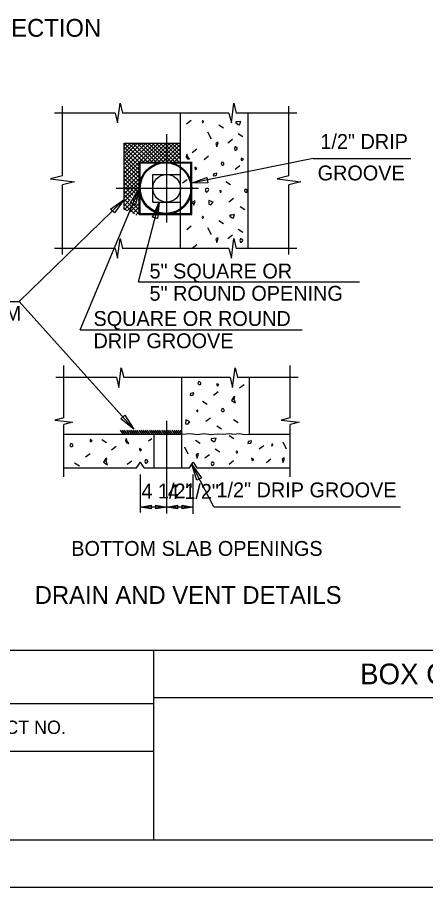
# Model space of a CAD drawing. Extents: x 0 to 34, y 0 to 23.5.
# Drawn here: x 20.81 to 25.11, y 0 to 9.16 of the extents above; entities that cross this region are included whole.
import ezdxf

# ---------------------------------------------------------------- set-up
doc = ezdxf.new("R2010")
doc.units = 0
for name, color, linetype in [('BORDER_ANNO_Cutsheet', 7, 'Continuous'), ('BRDG_ANNO_Anno-Sheet', 7, 'Continuous'), ('BRDG_ANNO_General-Notes', 7, 'Continuous'), ('BRDG_BASE_Dtlctrln', 7, 'Continuous'), ('BRDG_BASE_Hidden-Line', 7, 'Continuous'), ('BRDG_BASE_Obj-Line', 7, 'Continuous'), ('BRDG_BASE_Pattern', 7, 'Continuous')]:
    doc.layers.add(name, color=color, linetype=linetype)

msp = doc.modelspace()

# ---------------------------------------------------------------- linework, layer by layer
at = {"layer": 'BORDER_ANNO_Cutsheet'}
msp.add_lwpolyline([(0, 22), (34, 22), (34, 0), (0, 0)], close=True, dxfattribs=at)
at = {"layer": 'BRDG_ANNO_Anno-Sheet'}
for p, q in [((19.25, 2.5), (33.5, 2.5)), ((22.25, 0.5), (22.25, 2.5)), ((19.25, 1.9375), (22.25, 1.9375)), ((22.25, 2), (30.25, 2)), ((19.25, 1.4375), (22.25, 1.4375))]:
    msp.add_line(p, q, dxfattribs=at)
msp.add_lwpolyline([(1.5, 21.5), (33.5, 21.5), (33.5, 0.5), (1.5, 0.5)], close=True, dxfattribs=at)
at = {"layer": 'BRDG_ANNO_General-Notes'}
for p, q in [((23.9302, 7.6753), (22.6452, 7.4156)), ((23.9302, 7.6753), (24.9576, 7.6753)), ((22.6452, 7.4156), (22.8071, 7.4774)), ((22.8184, 7.4215), (22.6452, 7.4156)), ((22.8071, 7.4774), (22.8184, 7.4215)), ((21.4729, 5.8739), (22.0956, 7.3578)), ((22.0032, 7.2111), (22.0956, 7.3578)), ((22.0956, 7.3578), (22.0557, 7.1891)), ((20.8304, 6.1721), (21.9379, 7.2429)), ((21.7952, 7.1445), (21.9379, 7.2429)), ((21.9379, 7.2429), (21.8347, 7.1036)), ((22.0557, 7.1891), (22.0032, 7.2111)), ((22.0894, 6.3784), (22.3048, 7.2174)), ((22.2347, 7.0589), (22.3048, 7.2174)), ((22.3048, 7.2174), (22.2899, 7.0447)), ((21.8347, 7.1036), (21.7952, 7.1445)), ((22.2899, 7.0447), (22.2347, 7.0589)), ((22.0894, 6.3784), (24.4154, 6.3784)), ((19.5549, 6.1721), (20.8304, 6.1721)), ((20.8304, 6.1721), (22.0379, 4.826)), ((21.4729, 5.8739), (23.8114, 5.8739)), ((21.9024, 4.9343), (21.9449, 4.9723)), ((21.9449, 4.9723), (22.0379, 4.826)), ((22.0379, 4.826), (21.9024, 4.9343)), ((22.8813, 4.0103), (22.6494, 4.4538)), ((22.7034, 4.2891), (22.6494, 4.4538)), ((22.6494, 4.4538), (22.7539, 4.3155)), ((22.1087, 3.9479), (22.1087, 4.3503)), ((22.6629, 3.9363), (22.6629, 4.3503)), ((22.7539, 4.3155), (22.7034, 4.2891)), ((22.1069, 4.0066), (22.2209, 4.0256)), ((22.2209, 3.9876), (22.1069, 4.0066)), ((22.1087, 4.0075), (22.6629, 4.0075)), ((22.2209, 4.0256), (22.2209, 3.9876)), ((22.2719, 3.9876), (22.2719, 4.0256)), ((22.2719, 4.0256), (22.3859, 4.0066)), ((22.3859, 4.0066), (22.2719, 3.9876)), ((22.3859, 4.0066), (22.4999, 4.0256)), ((22.4999, 3.9876), (22.3859, 4.0066)), ((22.4999, 4.0256), (22.4999, 3.9876)), ((22.5473, 3.9876), (22.5473, 4.0256)), ((22.5473, 4.0256), (22.6613, 4.0066)), ((22.6613, 4.0066), (22.5473, 3.9876)), ((22.8813, 4.0103), (24.8498, 4.0103))]:
    msp.add_line(p, q, dxfattribs=at)
at = {"layer": 'BRDG_BASE_Dtlctrln'}
for p, q in [((21.8548, 7.3632), (22.7191, 7.3632)), ((22.3858, 3.9403), (22.3858, 4.9129))]:
    msp.add_line(p, q, dxfattribs=at)
at = {"layer": 'BRDG_BASE_Hidden-Line'}
for p, q in [((22.0962, 7.6394), (22.6505, 7.6394)), ((22.0962, 7.0861), (22.0962, 7.6394)), ((22.1061, 7.0969), (22.1061, 7.6305)), ((22.1061, 7.6305), (22.6405, 7.6305)), ((22.6405, 7.0969), (22.6405, 7.6305)), ((22.6504, 7.0861), (22.6504, 7.6403)), ((22.0962, 7.0856), (22.6504, 7.0856)), ((22.1061, 7.0969), (22.6405, 7.0969))]:
    msp.add_line(p, q, dxfattribs=at)
for centre, radius in [((22.3733, 7.3622), 0.2771), ((22.3733, 7.3643), 0.2672)]:
    msp.add_circle(centre, radius, dxfattribs=at)
at = {"layer": 'BRDG_BASE_Obj-Line'}
for p, q in [((21.8691, 8.0507), (21.8952, 8.2591)), ((21.8952, 8.2591), (21.9212, 8.1549)), ((23.067, 8.0507), (23.0931, 8.2591)), ((23.0931, 8.2591), (23.1191, 8.1549)), ((21.8431, 8.1549), (21.2051, 8.1549)), ((21.2884, 7.4934), (21.2884, 8.2278)), ((21.8431, 8.1549), (21.8691, 8.0507)), ((23.041, 8.1549), (21.9212, 8.1549)), ((22.5316, 6.7299), (22.5316, 8.1549)), ((23.041, 8.1549), (23.067, 8.0507)), ((23.7571, 8.1549), (23.1191, 8.1549)), ((23.2441, 6.7299), (23.2441, 8.1549)), ((23.6738, 7.4934), (23.6738, 8.2278)), ((22.3858, 7.0032), (22.3858, 7.932)), ((21.9379, 7.8382), (22.5316, 7.8382)), ((21.9379, 7.1402), (21.9379, 7.8382)), ((22.5129, 7.8382), (22.5316, 7.8382)), ((21.2884, 7.4934), (21.1634, 7.4622)), ((21.1634, 7.4622), (21.4134, 7.4309)), ((21.4134, 7.4309), (21.2884, 7.3997)), ((22.2399, 7.5091), (22.5316, 7.5091)), ((22.2399, 7.2174), (22.2399, 7.5091)), ((23.6738, 7.4934), (23.5488, 7.4622)), ((23.5488, 7.4622), (23.7988, 7.4309)), ((23.7988, 7.4309), (23.6738, 7.3997)), ((21.2884, 6.6653), (21.2884, 7.3997)), ((23.6738, 6.6653), (23.6738, 7.3997)), ((22.2399, 7.2174), (22.5316, 7.2174)), ((21.8691, 6.6257), (21.8952, 6.8341)), ((21.8952, 6.8341), (21.9212, 6.7299)), ((23.067, 6.6257), (23.0931, 6.8341)), ((23.0931, 6.8341), (23.1191, 6.7299)), ((21.8431, 6.7299), (21.2051, 6.7299)), ((21.8431, 6.7299), (21.8691, 6.6257)), ((23.041, 6.7299), (21.9212, 6.7299)), ((23.041, 6.7299), (23.067, 6.6257)), ((23.7571, 6.7299), (23.1191, 6.7299)), ((21.3009, 4.9459), (21.3009, 5.4967)), ((21.8816, 5.2649), (21.9077, 5.4732)), ((21.9077, 5.4732), (21.9337, 5.3691)), ((23.0795, 5.2649), (23.1056, 5.4732)), ((23.1056, 5.4732), (23.1316, 5.3691)), ((23.6863, 4.9459), (23.6863, 5.4967)), ((21.8556, 5.3691), (21.2176, 5.3691)), ((21.8556, 5.3691), (21.8816, 5.2649)), ((23.0535, 5.3691), (21.9337, 5.3691)), ((22.5441, 4.4191), (22.5441, 5.3691)), ((23.0535, 5.3691), (23.0795, 5.2649)), ((23.7696, 5.3691), (23.1316, 5.3691)), ((23.2566, 4.7753), (23.2566, 5.3691)), ((21.3009, 4.9459), (21.2071, 4.9224)), ((21.2071, 4.9224), (21.3946, 4.899)), ((21.3946, 4.899), (21.3009, 4.8756)), ((21.3009, 4.3248), (21.3009, 4.8756)), ((23.6863, 4.9459), (23.5926, 4.9224)), ((23.5926, 4.9224), (23.7801, 4.899)), ((23.7801, 4.899), (23.6863, 4.8756)), ((23.6863, 4.3248), (23.6863, 4.8756)), ((21.3009, 4.7753), (22.5441, 4.7753)), ((22.2524, 4.4191), (22.2524, 4.7753)), ((23.2566, 4.7753), (23.6863, 4.7753)), ((21.3009, 4.4191), (22.069, 4.4191)), ((22.069, 4.4191), (22.1087, 4.4774)), ((22.1478, 4.4186), (22.1087, 4.4774)), ((22.1478, 4.4191), (22.6251, 4.4191)), ((22.6251, 4.4191), (22.6629, 4.4774)), ((22.6629, 4.4774), (22.7035, 4.4179)), ((22.7035, 4.4191), (23.6863, 4.4191))]:
    msp.add_line(p, q, dxfattribs=at)
for points in [[(22.5441, 4.7753), (22.6369, 4.7807), (22.7074, 4.7706), (22.7797, 4.7799), (22.8485, 4.7706), (22.919, 4.7791), (22.9829, 4.7723), (23.0433, 4.7807), (23.092, 4.7723), (23.1507, 4.7799), (23.2079, 4.7706), (23.2566, 4.7753)], [(23.2566, 4.7753), (23.2548, 4.7755)]]:
    msp.add_lwpolyline(points, dxfattribs=at)
msp.add_circle((22.3858, 7.3632), 0.1458, dxfattribs=at)
at = {"layer": 'BRDG_BASE_Pattern'}
for p, q in [((22.6423, 8.0756), (22.5942, 8.039)), ((22.9335, 8.0292), (22.983, 7.998)), ((22.816, 7.9584), (22.8527, 7.8849)), ((23.1399, 7.9389), (23.1894, 7.9077)), ((21.9377, 7.8092), (21.967, 7.8385)), ((21.938, 7.796), (22.0963, 7.6386)), ((21.9387, 7.8391), (22.1392, 7.6397)), ((21.9389, 7.6568), (22.121, 7.838)), ((21.9401, 7.7734), (22.0052, 7.8382)), ((21.9404, 7.7373), (22.0423, 7.8387)), ((21.9416, 7.7017), (22.0787, 7.8382)), ((21.9668, 7.6409), (22.1652, 7.8382)), ((21.9842, 7.8388), (22.1821, 7.6418)), ((22.0119, 7.6409), (22.211, 7.8389)), ((22.0306, 7.8377), (22.2279, 7.6412)), ((22.0572, 7.6409), (22.256, 7.8389)), ((22.0736, 7.837), (22.2707, 7.6409)), ((22.0996, 7.6409), (22.2981, 7.8384)), ((22.113, 7.8388), (22.3115, 7.6414)), ((22.1394, 7.6395), (22.3396, 7.8385)), ((22.1554, 7.8382), (22.3532, 7.6414)), ((22.1826, 7.6409), (22.3816, 7.8387)), ((22.1954, 7.8372), (22.3927, 7.6409)), ((22.2216, 7.6409), (22.4198, 7.8381)), ((22.2336, 7.8385), (22.4323, 7.6409)), ((22.2612, 7.6409), (22.4593, 7.8379)), ((22.2753, 7.8378), (22.4748, 7.6394)), ((22.3021, 7.6409), (22.5001, 7.8377)), ((22.3179, 7.8383), (22.5179, 7.6394)), ((22.3452, 7.6409), (22.5311, 7.8258)), ((22.3598, 7.8386), (22.5316, 7.6677)), ((22.4006, 7.8377), (22.5316, 7.7075)), ((22.4406, 7.8387), (22.5316, 7.7481)), ((22.4808, 7.8382), (22.5303, 7.789)), ((23.0794, 7.8758), (23.0313, 7.8392)), ((21.9379, 7.754), (22.0964, 7.5962)), ((21.9383, 7.712), (22.0962, 7.555)), ((22.3876, 7.6409), (22.5316, 7.7841)), ((22.4273, 7.6409), (22.5316, 7.7447)), ((22.4683, 7.6409), (22.5317, 7.7039)), ((22.7028, 7.7739), (22.6547, 7.7372)), ((22.8271, 7.6999), (22.779, 7.6633)), ((21.937, 7.6334), (22.0961, 7.4753)), ((21.9372, 7.5215), (22.0572, 7.6409)), ((21.9372, 7.4792), (22.0962, 7.6375)), ((21.9375, 7.5667), (22.0119, 7.6409)), ((21.9379, 7.6121), (21.9668, 7.6409)), ((21.938, 7.673), (22.0959, 7.5161)), ((22.0982, 7.6394), (22.0996, 7.6409)), ((22.5238, 7.6406), (22.5321, 7.6489)), ((21.9371, 7.4335), (22.0962, 7.5918)), ((21.9372, 7.3904), (22.0961, 7.5484)), ((21.938, 7.5903), (22.096, 7.4334)), ((21.9384, 7.5466), (22.0963, 7.3896)), ((23.156, 7.5975), (23.1079, 7.5609)), ((21.9369, 7.3456), (22.0961, 7.5039)), ((21.9369, 7.2636), (22.0961, 7.4219)), ((21.9373, 7.4236), (22.0519, 7.3098)), ((21.9377, 7.4646), (22.0707, 7.3324)), ((21.9379, 7.3036), (22.0964, 7.4612)), ((21.938, 7.5059), (22.096, 7.349)), ((22.601, 7.4532), (22.5529, 7.4166)), ((23.0078, 7.4335), (23.0573, 7.4023)), ((21.938, 7.3813), (22.0326, 7.2874)), ((21.938, 7.3369), (22.0144, 7.261)), ((21.9387, 7.2234), (22.0971, 7.381)), ((21.9377, 7.2474), (22.0965, 7.0896)), ((21.938, 7.2921), (21.9966, 7.234)), ((21.9383, 7.1796), (22.0024, 7.2434)), ((22.0285, 7.2469), (22.0635, 7.2121)), ((22.0314, 7.2288), (22.0765, 7.274)), ((22.0464, 7.2737), (22.0708, 7.2494)), ((22.0617, 7.3001), (22.0783, 7.2836)), ((22.0863, 7.2414), (22.0961, 7.2511)), ((22.0869, 7.2751), (22.0962, 7.2658)), ((22.0891, 7.2866), (22.0962, 7.2936)), ((22.0919, 7.3115), (22.0962, 7.3071)), ((23.0897, 7.2549), (23.0416, 7.2183)), ((21.9373, 7.1534), (21.9656, 7.1253)), ((21.9384, 7.2006), (22.047, 7.0926)), ((21.939, 7.1373), (22.019, 7.2168)), ((21.974, 7.1296), (22.0485, 7.2037)), ((22.0021, 7.1136), (22.0964, 7.2074)), ((22.0129, 7.2178), (22.0962, 7.135)), ((22.0304, 7.0982), (22.0954, 7.163)), ((22.0595, 7.2146), (22.0693, 7.2244)), ((22.0787, 7.197), (22.096, 7.1799)), ((22.0849, 7.2354), (22.096, 7.2244)), ((23.1586, 7.1717), (23.2082, 7.1404)), ((22.0589, 7.0809), (22.0961, 7.1179)), ((22.9335, 7.0219), (22.983, 6.9906)), ((22.6445, 6.9622), (22.5964, 6.9256)), ((22.816, 6.9511), (22.8527, 6.8776)), ((23.1399, 6.9316), (23.1894, 6.9003)), ((23.0794, 6.8684), (23.0313, 6.8318)), ((22.7028, 6.7665), (22.6547, 6.7299)), ((23.2006, 5.2935), (23.1524, 5.2569)), ((22.927, 5.2188), (22.8789, 5.1822)), ((22.764, 5.1227), (22.8135, 5.0915)), ((22.8459, 4.9441), (22.7978, 4.9074)), ((22.9148, 4.8608), (22.9644, 4.8296)), ((23.0884, 4.9291), (23.1378, 4.8981)), ((21.8956, 4.8149), (21.9235, 4.7762)), ((21.9172, 4.8149), (21.9452, 4.7763)), ((21.939, 4.8149), (21.9669, 4.7763)), ((21.9607, 4.8149), (21.9886, 4.7763)), ((21.9824, 4.815), (22.0103, 4.7763)), ((22.0041, 4.815), (22.032, 4.7763)), ((22.0258, 4.815), (22.0537, 4.7763)), ((22.0475, 4.8151), (22.0754, 4.7764)), ((22.0692, 4.8151), (22.0971, 4.7764)), ((22.0909, 4.8151), (22.1189, 4.7764)), ((22.1127, 4.8151), (22.1405, 4.7764)), ((22.1344, 4.8151), (22.1622, 4.7764)), ((22.1561, 4.8151), (22.184, 4.7764)), ((22.1778, 4.8152), (22.2057, 4.7765)), ((22.1995, 4.8152), (22.2274, 4.7765)), ((22.2212, 4.8152), (22.2491, 4.7765)), ((22.2429, 4.8152), (22.2708, 4.7765)), ((22.2646, 4.8152), (22.2926, 4.7765)), ((22.2864, 4.8152), (22.3143, 4.7765)), ((22.3081, 4.8152), (22.336, 4.7765)), ((22.3297, 4.8153), (22.3577, 4.7766)), ((22.3515, 4.8153), (22.3794, 4.7766)), ((22.3732, 4.8153), (22.4011, 4.7766)), ((22.3949, 4.8153), (22.4228, 4.7766)), ((22.4166, 4.8153), (22.4445, 4.7766)), ((22.4385, 4.8149), (22.4665, 4.7762)), ((22.4603, 4.8149), (22.4882, 4.7762)), ((22.481, 4.8149), (22.509, 4.7762)), ((22.5034, 4.8149), (22.5313, 4.7762)), ((22.5241, 4.8149), (22.5441, 4.7872)), ((21.7008, 4.7165), (21.7503, 4.6852)), ((22.2274, 4.7255), (22.1957, 4.7014)), ((22.6897, 4.711), (22.7392, 4.6798)), ((23.0434, 4.7601), (23.0929, 4.7288)), ((23.6075, 4.6941), (23.6442, 4.6205)), ((21.8528, 4.6424), (21.8046, 4.6058)), ((22.5722, 4.6403), (22.6089, 4.5667)), ((22.8961, 4.6207), (22.9456, 4.5895)), ((23.4091, 4.6514), (23.3609, 4.6147)), ((21.5792, 4.5677), (21.5311, 4.5311)), ((22.0178, 4.4912), (21.9697, 4.4546)), ((22.8356, 4.5576), (22.7875, 4.521)), ((23.0903, 4.4926), (23.0421, 4.456)), ((23.4835, 4.5095), (23.4354, 4.4729)), ((21.4162, 4.4716), (21.4657, 4.4404))]:
    msp.add_line(p, q, dxfattribs=at)
for points in [[(22.7591, 8.0634), (22.762, 8.0542), (22.7646, 8.0542), (22.7684, 8.0552), (22.7711, 8.0578), (22.7737, 8.0634), (22.773, 8.069), (22.7684, 8.0699), (22.7664, 8.0718), (22.7628, 8.0718)], [(23.1377, 8.063), (23.1156, 8.0611), (23.1156, 8.0501), (23.1395, 8.0335), (23.1525, 8.0317), (23.1654, 8.0666)], [(22.9021, 7.8336), (22.9135, 7.8004), (22.9135, 7.804), (22.9282, 7.841), (22.9244, 7.8483)], [(23.0987, 7.7819), (23.1045, 7.7635), (23.1098, 7.7635), (23.1173, 7.7653), (23.1228, 7.7707), (23.1281, 7.7819), (23.1266, 7.7929), (23.1173, 7.7948), (23.1134, 7.7986), (23.1061, 7.7986)], [(22.5936, 7.7145), (22.5896, 7.6938), (22.6033, 7.6735), (22.6264, 7.669), (22.608, 7.6933), (22.6001, 7.7186)], [(22.9674, 7.6379), (22.9582, 7.6177), (22.969, 7.6064), (22.9822, 7.6064), (22.9877, 7.6123), (22.9877, 7.6231), (22.9858, 7.6284), (22.9801, 7.6343)], [(23.1704, 7.6795), (23.1695, 7.6597), (23.1815, 7.6569), (23.193, 7.6703)], [(22.6827, 7.5859), (22.6864, 7.5601), (22.7048, 7.5712)], [(22.8805, 7.5143), (22.8768, 7.4922), (22.9026, 7.4959), (22.9099, 7.4995), (22.9136, 7.5217)], [(22.7961, 7.3583), (22.7961, 7.3304), (22.8087, 7.3214), (22.8126, 7.325), (22.8234, 7.3361), (22.8308, 7.3509), (22.8255, 7.3583), (22.8181, 7.3618), (22.8145, 7.3618), (22.8072, 7.3598)], [(22.949, 7.3385), (22.9444, 7.3284), (22.9498, 7.3228), (22.9564, 7.3228), (22.9591, 7.3257), (22.9591, 7.3311), (22.9582, 7.3337), (22.9554, 7.3367)], [(23.2135, 7.3541), (23.2042, 7.3339), (23.2151, 7.3227), (23.2283, 7.3227), (23.2337, 7.3285), (23.2337, 7.3393), (23.2319, 7.3446), (23.2261, 7.3506)], [(22.6585, 7.217), (22.6699, 7.1838), (22.6699, 7.1873), (22.6846, 7.2244), (22.6808, 7.2317)], [(22.8298, 7.2346), (22.828, 7.195), (22.8519, 7.1894), (22.8749, 7.2161)], [(22.7591, 7.0561), (22.762, 7.0469), (22.7646, 7.0469), (22.7684, 7.0478), (22.7711, 7.0505), (22.7737, 7.0561), (22.773, 7.0616), (22.7684, 7.0626), (22.7664, 7.0645), (22.7628, 7.0645)], [(23.0733, 7.0814), (23.0512, 7.0795), (23.0512, 7.0685), (23.0752, 7.052), (23.0881, 7.0501), (23.101, 7.0851)], [(22.9021, 6.8263), (22.9135, 6.7931), (22.9135, 6.7967), (22.9282, 6.8336), (22.9244, 6.841)], [(23.1567, 6.8133), (23.1625, 6.7948), (23.1678, 6.7948), (23.1753, 6.7967), (23.1807, 6.802), (23.1861, 6.8133), (23.1846, 6.8242), (23.1753, 6.8261), (23.1714, 6.8299), (23.1641, 6.8299)], [(22.7236, 5.327), (22.7144, 5.3068), (22.7252, 5.2956), (22.7384, 5.2956), (22.7439, 5.3015), (22.7439, 5.3122), (22.742, 5.3176), (22.7363, 5.3235)], [(22.9131, 5.3056), (22.9122, 5.2858), (22.9242, 5.2831), (22.9357, 5.2964)], [(22.6367, 5.2034), (22.633, 5.1814), (22.6588, 5.1851), (22.6661, 5.1887), (22.6698, 5.2108)], [(23.094, 5.1678), (23.0682, 5.1292), (23.1115, 5.1033), (23.0957, 5.1383), (23.1024, 5.1704)], [(22.9697, 5.0433), (22.9604, 5.0231), (22.9712, 5.0118), (22.9845, 5.0118), (22.9899, 5.0177), (22.9899, 5.0285), (22.9881, 5.0338), (22.9823, 5.0397)], [(22.7052, 5.0277), (22.7006, 5.0176), (22.706, 5.0119), (22.7126, 5.0119), (22.7153, 5.0148), (22.7153, 5.0203), (22.7144, 5.0229), (22.7116, 5.0259)], [(22.586, 4.9238), (22.5842, 4.8842), (22.6081, 4.8786), (22.6311, 4.9053)], [(21.3758, 4.6759), (21.3666, 4.6557), (21.3774, 4.6445), (21.3906, 4.6445), (21.396, 4.6504), (21.396, 4.6611), (21.3942, 4.6665), (21.3885, 4.6724)], [(21.5788, 4.7176), (21.5779, 4.6978), (21.5898, 4.695), (21.6014, 4.7083)], [(21.9553, 4.723), (21.9512, 4.7023), (21.9649, 4.682), (21.988, 4.6774), (21.9696, 4.7018), (21.9617, 4.7271)], [(22.8779, 4.7276), (22.8558, 4.7257), (22.8558, 4.7146), (22.8797, 4.6981), (22.8927, 4.6963), (22.9056, 4.7312)], [(23.2456, 4.6976), (23.2419, 4.6756), (23.2678, 4.6793), (23.2751, 4.6829), (23.2787, 4.705)], [(22.0994, 4.624), (22.1031, 4.5982), (22.1216, 4.6093)], [(23.1217, 4.5946), (23.1171, 4.5845), (23.1225, 4.5789), (23.1291, 4.5789), (23.1318, 4.5818), (23.1318, 4.5872), (23.1309, 4.5899), (23.1281, 4.5929)], [(23.4893, 4.6614), (23.4922, 4.6522), (23.4949, 4.6522), (23.4986, 4.6531), (23.5014, 4.6558), (23.504, 4.6614), (23.5033, 4.6669), (23.4986, 4.6679), (23.4967, 4.6698), (23.493, 4.6698)], [(21.7461, 4.5167), (21.7204, 4.4781), (21.7637, 4.4522), (21.7479, 4.4872), (21.7546, 4.5193)], [(22.1566, 4.4877), (22.1624, 4.4692), (22.1677, 4.4692), (22.1752, 4.471), (22.1806, 4.4764), (22.186, 4.4877), (22.1845, 4.4986), (22.1752, 4.5005), (22.1713, 4.5043), (22.164, 4.5043)], [(22.6955, 4.5547), (22.7069, 4.5215), (22.7069, 4.5251), (22.7216, 4.562), (22.7179, 4.5694)], [(23.2806, 4.5209), (23.2843, 4.4951), (23.3028, 4.5061)], [(23.6022, 4.509), (23.6136, 4.4758), (23.6136, 4.4794), (23.6283, 4.5164), (23.6246, 4.5237)], [(22.8549, 4.4638), (22.8607, 4.4453), (22.866, 4.4453), (22.8735, 4.4471), (22.879, 4.4525), (22.8843, 4.4638), (22.8828, 4.4747), (22.8735, 4.4766), (22.8696, 4.4804), (22.8623, 4.4804)]]:
    msp.add_lwpolyline(points, close=True, dxfattribs=at)

# ---------------------------------------------------------------- texts
at = {"layer": 'BRDG_ANNO_Anno-Sheet'}
for s, height, p in [('BOX GIRDER DETAILS', 0.218126, (24.4227, 2.1406)), ('PROJECT NO.', 0.140625, (20.0591, 1.6175))]:
    msp.add_text(s, height=height, dxfattribs=at).set_placement(p)
at = {"layer": 'BRDG_ANNO_General-Notes'}
for s, height, p in [('INTERMEDIATE DIAPHRAGM SECTION', 0.1875, (17.056, 8.9581)), ('1/2" DRIP', 0.15625, (24.0047, 7.7774)), ('GROOVE', 0.15625, (23.9755, 7.446)), ('5" SQUARE OR', 0.15625, (22.2047, 6.4132)), ('5" ROUND OPENING', 0.15625, (22.2047, 6.1788)), ('ALUMINUM', 0.15625, (19.7393, 5.9686)), ('SQUARE OR ROUND', 0.15625, (21.6147, 5.9137)), ('DRIP GROOVE', 0.15625, (21.6147, 5.6793)), ('1/2" DRIP GROOVE', 0.15625, (22.9099, 4.1089)), ('BOTTOM SLAB OPENINGS', 0.15625, (21.3806, 3.4927)), ('DRAIN AND VENT DETAILS', 0.1875, (20.9956, 2.9868))]:
    msp.add_text(s, height=height, dxfattribs=at).set_placement(p)
for p in [(22.1198, 4.0952), (22.3973, 4.0905)]:
    msp.add_text('4 1/2"', height=0.15625, rotation=0.41637, dxfattribs=at).set_placement(p)

doc.saveas('drawing.dxf')
